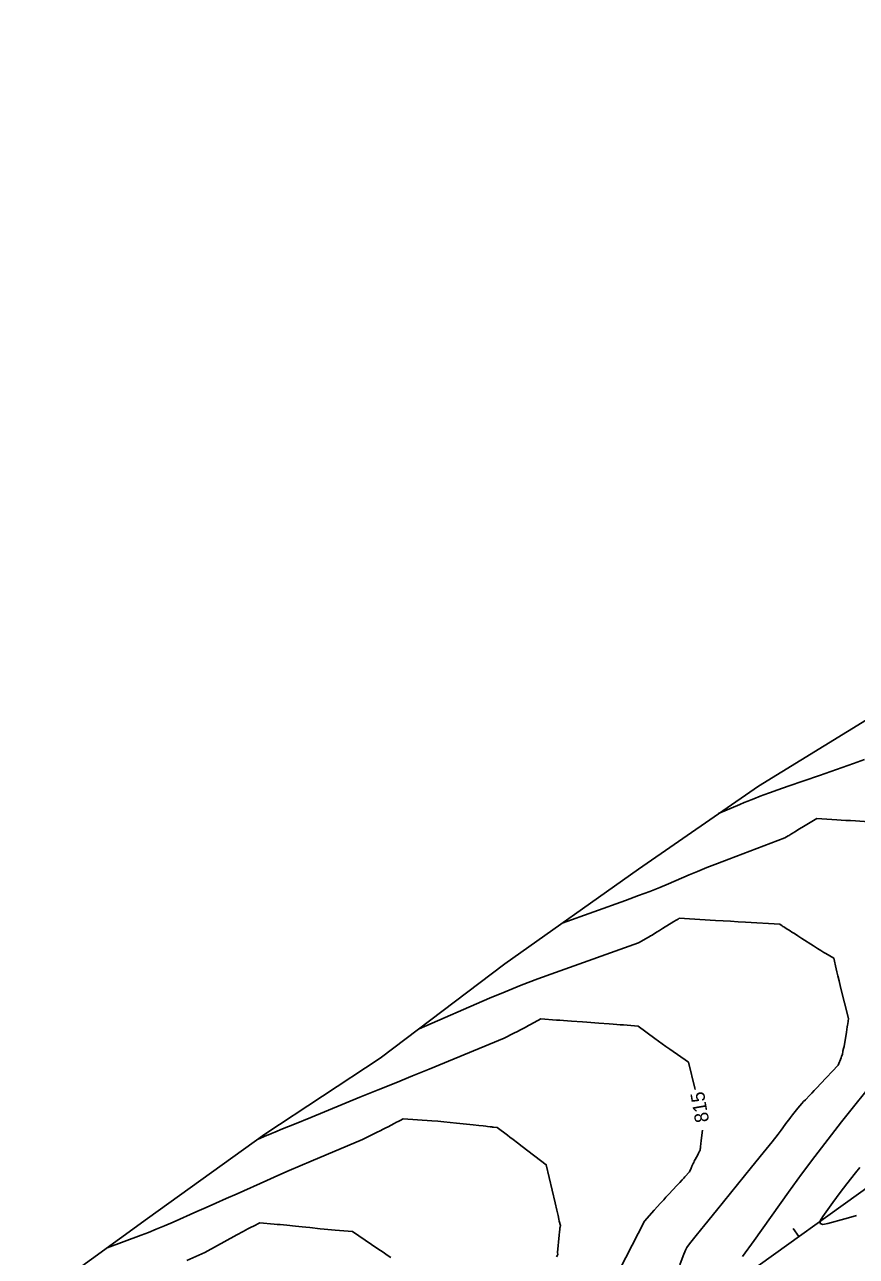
# Model space of a CAD drawing. Extents: x 2079879 to 2092887, y 778083 to 784051.
# Drawn here: x 2084034.7 to 2084202.5, y 781138.5 to 781386.8 of the extents above; entities that cross this region are included whole.
import ezdxf

# ---------------------------------------------------------------- set-up
doc = ezdxf.new("R2010")
doc.units = 0
for name, color, linetype in [('DT_X_Contour_Major', 7, 'Continuous'), ('DT_X_Contour_Minor', 7, 'Continuous'), ('DT_X_TIN_Hull', 7, 'Continuous'), ('GE_X_CL_20', 7, 'Continuous')]:
    doc.layers.add(name, color=color, linetype=linetype)

msp = doc.modelspace()

# ---------------------------------------------------------------- linework, layer by layer
at = {"layer": 'DT_X_Contour_Major'}
for points in [[(2084081.74, 781162.02), (2084082.92, 781162.54), (2084083.17, 781162.66), (2084083.42, 781162.76), (2084083.66, 781162.87), (2084083.91, 781162.97), (2084084.55, 781163.25), (2084085.23, 781163.53), (2084086.78, 781164.16), (2084089.19, 781165.14), (2084092.48, 781166.48), (2084102.39, 781170.53), (2084106.05, 781172.02), (2084109.6, 781173.47), (2084113.02, 781174.87), (2084116.34, 781176.23), (2084131.52, 781182.45), (2084133.43, 781183.44), (2084134.17, 781183.83), (2084134.76, 781184.13), (2084135.44, 781184.49), (2084135.72, 781184.63), (2084136.04, 781184.8), (2084136.41, 781185), (2084136.83, 781185.23), (2084138.87, 781186.33), (2084142.03, 781186.11), (2084142.72, 781186.06), (2084143.46, 781186), (2084144.24, 781185.95), (2084145.06, 781185.89), (2084147.31, 781185.72), (2084148.14, 781185.66), (2084148.97, 781185.6), (2084149.78, 781185.54), (2084150.58, 781185.48), (2084152.69, 781185.32), (2084153.46, 781185.26), (2084154.2, 781185.21), (2084154.9, 781185.16), (2084155.55, 781185.11), (2084158.54, 781184.9), (2084161.88, 781182.41), (2084162.61, 781181.88), (2084163.36, 781181.33), (2084164.13, 781180.78), (2084164.93, 781180.22), (2084168.71, 781177.58), (2084169.98, 781172.35), (2084170.04, 781172.12)], [(2084171.48, 781163.91), (2084171.24, 781161.8), (2084171.17, 781161.12), (2084171.11, 781160.62), (2084171.07, 781160.3), (2084171.06, 781160.16), (2084171.03, 781159.9), (2084170.95, 781159.75), (2084170.91, 781159.67), (2084170.83, 781159.52), (2084170.7, 781159.28), (2084170.54, 781158.95), (2084170.03, 781157.98), (2084169.85, 781157.64), (2084169.72, 781157.38), (2084169.62, 781157.18), (2084169.55, 781157.05), (2084169.43, 781156.79), (2084169.38, 781156.69), (2084169.33, 781156.57), (2084169.27, 781156.43), (2084169.2, 781156.27), (2084168.87, 781155.49), (2084167.97, 781154.52), (2084167.72, 781154.25), (2084167.37, 781153.87), (2084166.91, 781153.38), (2084166.35, 781152.76), (2084164.7, 781150.98), (2084164.13, 781150.37), (2084163.67, 781149.87), (2084163.31, 781149.48), (2084163.06, 781149.21), (2084161.77, 781147.78), (2084159.78, 781145.57), (2084153.57, 781133.35)]]:
    msp.add_lwpolyline(points, dxfattribs=at)
at = {"layer": 'DT_X_Contour_Minor'}
for points in [[(2084174.74, 781227.75), (2084179.03, 781229.59), (2084179.89, 781229.96), (2084180.65, 781230.27), (2084181.3, 781230.54), (2084181.84, 781230.75), (2084183.14, 781231.24), (2084183.86, 781231.5), (2084185.05, 781231.92), (2084186.7, 781232.5), (2084188.81, 781233.24), (2084195.08, 781235.41), (2084197.41, 781236.22), (2084199.71, 781237.03), (2084201.96, 781237.84), (2084204.18, 781238.64)], [(2084143.18, 781205.65), (2084155.98, 781210.24), (2084158.58, 781211.19), (2084160.89, 781212.06), (2084162.9, 781212.85), (2084164.62, 781213.57), (2084168.82, 781215.37), (2084170.5, 781216.08), (2084172.4, 781216.84), (2084174.5, 781217.67), (2084176.82, 781218.56), (2084188.11, 781222.83), (2084188.8, 781223.26), (2084188.96, 781223.35), (2084189.11, 781223.44), (2084189.27, 781223.54), (2084189.44, 781223.65), (2084189.9, 781223.93), (2084190.13, 781224.07), (2084190.48, 781224.28), (2084190.95, 781224.57), (2084191.53, 781224.92), (2084194.54, 781226.77), (2084198.62, 781226.5), (2084199.5, 781226.44), (2084200.43, 781226.38), (2084201.38, 781226.32), (2084202.37, 781226.25), (2084205.04, 781226.08)], [(2084114.33, 781184.36), (2084128.55, 781190.49), (2084131.67, 781191.8), (2084134.92, 781193.11), (2084138.31, 781194.41), (2084141.83, 781195.7), (2084158.6, 781201.71), (2084160.16, 781202.58), (2084160.48, 781202.76), (2084160.77, 781202.92), (2084161.02, 781203.07), (2084161.23, 781203.19), (2084161.76, 781203.52), (2084162.02, 781203.68), (2084162.38, 781203.9), (2084162.86, 781204.19), (2084163.45, 781204.55), (2084165.74, 781205.96), (2084166.16, 781206.22), (2084166.43, 781206.39), (2084166.56, 781206.47), (2084166.82, 781206.63), (2084174.1, 781206.21), (2084175.65, 781206.12), (2084177.18, 781206.03), (2084178.7, 781205.94), (2084180.19, 781205.85), (2084187.09, 781205.41), (2084187.6, 781205.08), (2084187.73, 781205), (2084187.91, 781204.89), (2084188.13, 781204.75), (2084188.4, 781204.58), (2084189.17, 781204.09), (2084189.53, 781203.86), (2084190.05, 781203.54), (2084190.71, 781203.11), (2084191.53, 781202.58), (2084193.9, 781201.05), (2084194.72, 781200.53), (2084195.4, 781200.1), (2084195.95, 781199.76), (2084196.37, 781199.51), (2084197.97, 781198.6), (2084198.47, 781196.41), (2084198.61, 781195.83), (2084198.8, 781195.03), (2084199.06, 781194.01), (2084199.37, 781192.76), (2084200.97, 781186.45), (2084200.81, 781185.37), (2084200.77, 781185.09), (2084200.71, 781184.71), (2084200.64, 781184.23), (2084200.54, 781183.66), (2084200.07, 781180.78), (2084199.9, 781180.16), (2084199.86, 781180.03), (2084199.83, 781179.9), (2084199.81, 781179.78), (2084199.79, 781179.66), (2084199.75, 781179.35), (2084199.72, 781179.21), (2084199.66, 781179.02), (2084199.57, 781178.79), (2084199.45, 781178.5), (2084198.84, 781177.04), (2084195.34, 781173.26), (2084194.64, 781172.51), (2084194.05, 781171.88), (2084193.55, 781171.36), (2084193.16, 781170.96), (2084192.25, 781170.05), (2084191.9, 781169.69), (2084191.53, 781169.28), (2084191.15, 781168.83), (2084190.75, 781168.34), (2084189.66, 781166.97), (2084189.26, 781166.47), (2084188.89, 781165.98), (2084188.54, 781165.51), (2084188.21, 781165.06), (2084187.36, 781163.87), (2084186.75, 781163.07), (2084185.55, 781161.56), (2084183.77, 781159.35), (2084181.4, 781156.42), (2084174.31, 781147.68), (2084171.96, 781144.78), (2084170.25, 781142.66), (2084169.16, 781141.31), (2084168.7, 781140.73), (2084168.32, 781140.21), (2084168.07, 781139.7), (2084167.6, 781138.54), (2084166.91, 781136.73)], [(2084206.87, 781174.74), (2084199.56, 781165.57), (2084196.83, 781162.1), (2084194.14, 781158.58), (2084191.48, 781155.01), (2084188.86, 781151.4), (2084181.91, 781141.68), (2084179.59, 781138.44)], [(2084051.41, 781140.2), (2084058.22, 781142.7), (2084059.72, 781143.27), (2084061.31, 781143.91), (2084062.98, 781144.61), (2084064.73, 781145.37), (2084069.51, 781147.49), (2084071.37, 781148.31), (2084073.33, 781149.18), (2084075.41, 781150.11), (2084077.6, 781151.09), (2084083.61, 781153.76), (2084085.85, 781154.76), (2084088.09, 781155.74), (2084090.33, 781156.7), (2084092.55, 781157.64), (2084102.93, 781162.01), (2084105.87, 781163.48), (2084106.48, 781163.79), (2084107.05, 781164.08), (2084107.58, 781164.35), (2084108.07, 781164.6), (2084109.31, 781165.25), (2084109.74, 781165.48), (2084110.08, 781165.66), (2084110.34, 781165.79), (2084110.52, 781165.88), (2084111.13, 781166.21), (2084116.86, 781165.79), (2084118.09, 781165.69), (2084119.33, 781165.59), (2084120.59, 781165.47), (2084121.85, 781165.34), (2084125.23, 781164.99), (2084126.36, 781164.87), (2084127.22, 781164.78), (2084127.81, 781164.71), (2084128.13, 781164.67), (2084128.63, 781164.6), (2084128.81, 781164.57), (2084128.99, 781164.55), (2084129.16, 781164.53), (2084129.33, 781164.52), (2084130.1, 781164.45), (2084132.15, 781162.89), (2084132.66, 781162.5), (2084133.33, 781161.99), (2084134.15, 781161.37), (2084135.11, 781160.63), (2084139.99, 781156.93), (2084141.76, 781149.25), (2084142.1, 781147.79), (2084142.35, 781146.68), (2084142.52, 781145.95), (2084142.61, 781145.57), (2084142.82, 781144.66), (2084142.77, 781144.36), (2084142.75, 781144.21), (2084142.72, 781143.89), (2084142.67, 781143.4), (2084142.6, 781142.73), (2084142.27, 781139.23), (2084142.3, 781138.84), (2084142.25, 781138.68), (2084142.07, 781138.36)], [(2084203.23, 781156.35), (2084202.37, 781155.27), (2084200.61, 781153.07), (2084199.94, 781152.22), (2084199.25, 781151.3), (2084198.53, 781150.33), (2084197.79, 781149.3), (2084195.77, 781146.48), (2084195.26, 781145.6), (2084195.27, 781145.07), (2084195.78, 781144.89), (2084196.8, 781145.06), (2084200.2, 781146), (2084201.43, 781146.34), (2084202.58, 781146.68)], [(2084067.43, 781137.59), (2084071.1, 781139.22), (2084077.56, 781142.76), (2084078.81, 781143.45), (2084079.78, 781143.98), (2084080.47, 781144.35), (2084080.89, 781144.57), (2084082.21, 781145.24), (2084085.07, 781144.97), (2084085.69, 781144.91), (2084086.32, 781144.85), (2084086.96, 781144.78), (2084087.61, 781144.72), (2084089.36, 781144.55), (2084090.04, 781144.48), (2084090.74, 781144.41), (2084091.48, 781144.33), (2084092.25, 781144.24), (2084094.36, 781144), (2084095.14, 781143.92), (2084095.91, 781143.84), (2084096.67, 781143.77), (2084097.41, 781143.71), (2084100.86, 781143.44), (2084106.02, 781139.98), (2084107.05, 781139.3), (2084107.91, 781138.71), (2084108.62, 781138.23)]]:
    msp.add_lwpolyline(points, dxfattribs=at)
at = {"layer": 'DT_X_TIN_Hull'}
msp.add_lwpolyline([(2084420.64, 781401.06), (2084391.32, 781379.16), (2084366.83, 781361.2), (2084347.43, 781356.11), (2084344.84, 781360.3), (2084337.63, 781355.5), (2084342.14, 781349.52), (2084338.65, 781340.09), (2084313.15, 781322.64), (2084284.75, 781305.36), (2084260.97, 781288.46), (2084234.45, 781269.85), (2084209.3, 781249.55), (2084182.77, 781233.3), (2084158.56, 781216.56), (2084131.63, 781197.45), (2084106.47, 781178.42), (2084083.21, 781163.08), (2084059.54, 781146.11), (2084036.93, 781129.67)], dxfattribs=at)
at = {"layer": 'GE_X_CL_20'}
for p, q in [((2079923.52, 778084.44), (2085691.45, 782217.74)), ((2084190.94, 781142.47), (2084189.78, 781144.1))]:
    msp.add_line(p, q, dxfattribs=at)

# ---------------------------------------------------------------- texts
at = {"layer": 'DT_X_Contour_Major'}
msp.add_text('815', height=2.8, rotation=99.9252, dxfattribs=at).set_placement((2084172.85, 781165.68))

doc.saveas('drawing.dxf')
